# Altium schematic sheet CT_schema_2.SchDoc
size 461 x 297 mm
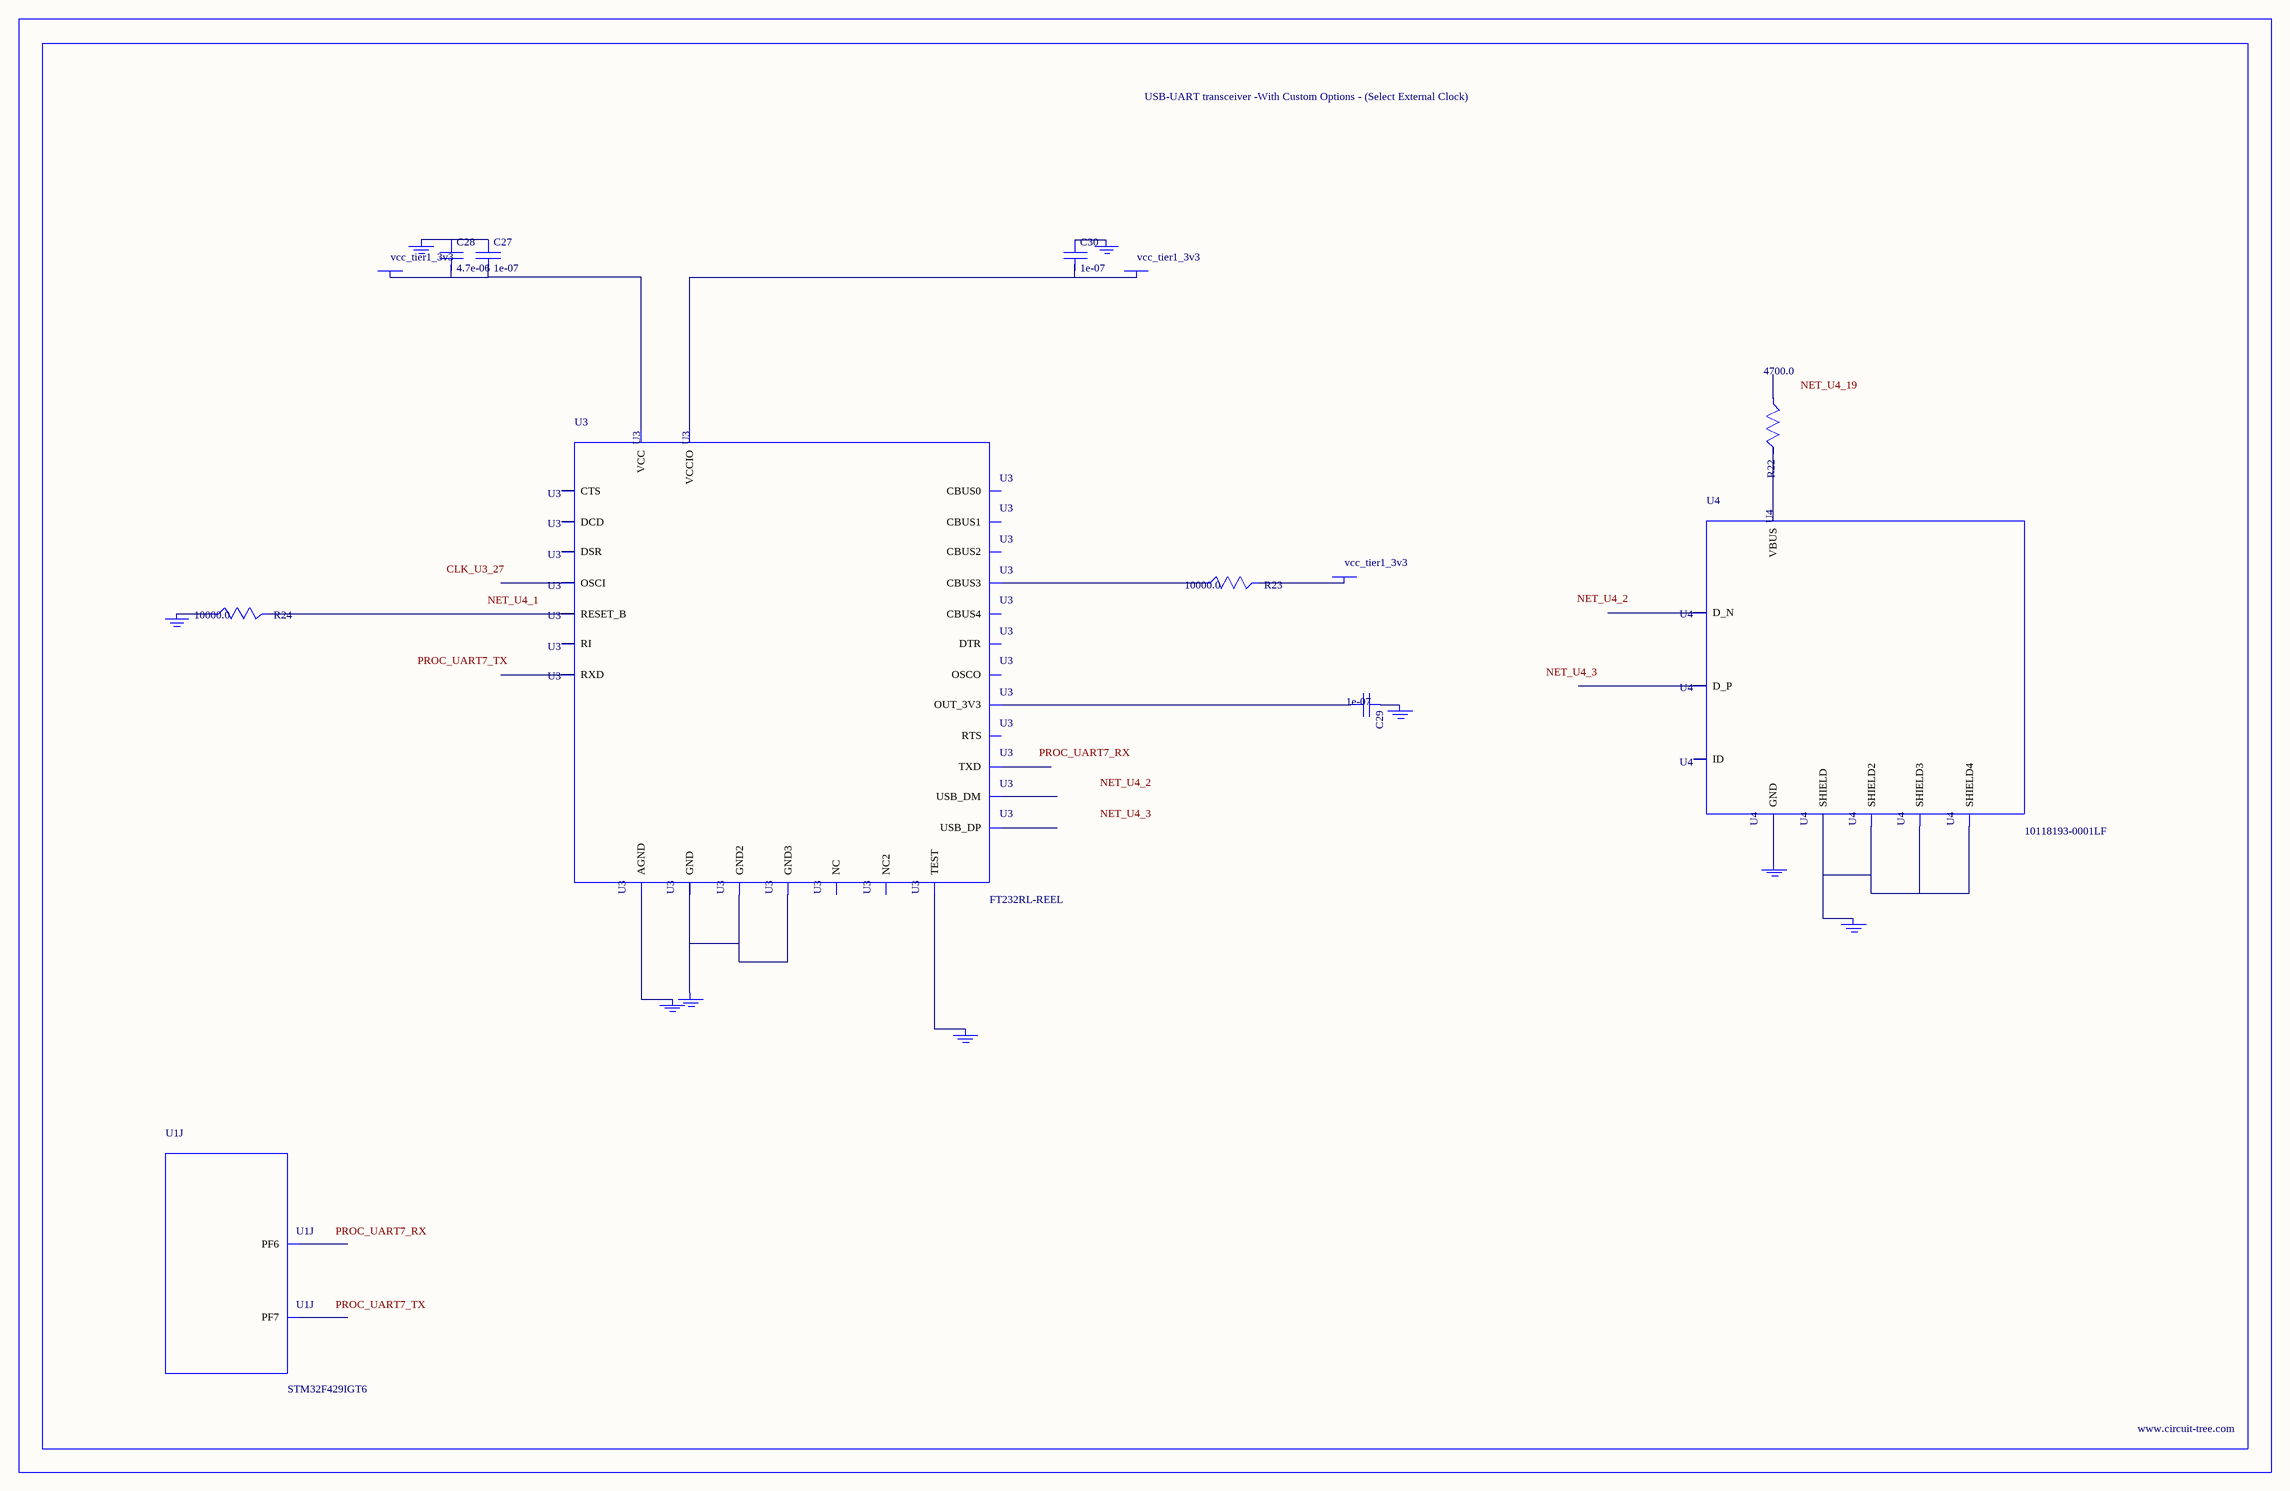
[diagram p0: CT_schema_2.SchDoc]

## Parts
BORDER1  (no value)
C27  1e-07  [C0402]
C28  4.7e-06  [C0805]
C29  1e-07  [C0402]
C30  1e-07  [C0402]
GND_INSTANCE_1_0  (no value)
GND_INSTANCE_1_1  (no value)
GND_INSTANCE_1_2  (no value)
GND_INSTANCE_1_3  (no value)
GND_INSTANCE_1_4  (no value)
GND_INSTANCE_1_5  (no value)
GND_INSTANCE_1_6  (no value)
GND_INSTANCE_1_7  (no value)
GND_INSTANCE_1_8  (no value)
POWER_INSTANCE_1_0  vcc_tier1_3v3
POWER_INSTANCE_1_1  vcc_tier1_3v3
POWER_INSTANCE_1_2  vcc_tier1_3v3
R22  4700.0  [R0603]
R23  10000.0  [R0603]
R24  10000.0  [R0603]
U1  STM32F429IGT6  [LQFP176]  (part J of 15)
U3  FT232RL-REEL  [SSOP-28]
U4  10118193-0001LF  [FCI_10118193-0001LF]

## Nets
NetC27_1: C27.1 C28.1 GND_INSTANCE_1_3.0(GND)
NetC27_2: C27.2 C28.2 POWER_INSTANCE_1_2.0(PWR) U3.20(VCC)
NetC29_1: C29.1 GND_INSTANCE_1_1.0(GND)
NetC29_2: C29.2 U3.17(OUT_3V3)
NetC30_1: C30.1 GND_INSTANCE_1_0.0(GND)
NetC30_2: C30.2 POWER_INSTANCE_1_0.0(PWR) U3.4(VCCIO)
NetGND_INSTANCE_1_2_0: GND_INSTANCE_1_2.0(GND) R24.1
NetGND_INSTANCE_1_4_0: GND_INSTANCE_1_4.0(GND) U3.25(AGND)
NetGND_INSTANCE_1_5_0: GND_INSTANCE_1_5.0(GND) U3.26(TEST)
NetGND_INSTANCE_1_6_0: GND_INSTANCE_1_6.0(GND) U3.7(GND) U3.18(GND2) U3.21(GND3)
NetGND_INSTANCE_1_7_0: GND_INSTANCE_1_7.0(GND) U4.6(SHIELD) U4.7(SHIELD2) U4.8(SHIELD3) U4.9(SHIELD4)
NetGND_INSTANCE_1_8_0: GND_INSTANCE_1_8.0(GND) U4.5(GND)
NetPOWER_INSTANCE_1_1_0: POWER_INSTANCE_1_1.0(PWR) R23.2
NetR22_2: R22.2 U4.1(VBUS)
NetR23_1: R23.1 U3.14(CBUS3)
NetR24_2: R24.2 U3.19(RESET_B)

Not connected (* = marked no-connect by the designer): R22 1; U1 24(PF6) 25(PF7); U3 1(TXD) 2(DTR) 3(RTS) 5(RXD) 6(RI) 8(NC) 9(DSR) 10(DCD) 11(CTS) 12(CBUS4) 13(CBUS2) 15(USB_DP) 16(USB_DM) 22(CBUS1) 23(CBUS0) 24(NC2) 27(OSCI) 28(OSCO); U4 2(D_N) 3(D_P) 4(ID)

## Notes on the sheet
- Labels drawn without touching a wire or pin: CLK_U3_27, NET_U4_1, NET_U4_2, NET_U4_3, NET_U4_19, PROC_UART7_RX, PROC_UART7_TX

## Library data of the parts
BORDER1 = BORDER_PAGE1
C27 C29 C30 = C0402C104K3RACTU
C28 = C0805C475K4RACTU
GND_INSTANCE_1_0-GND_INSTANCE_1_8 = GND
POWER_INSTANCE_1_0-POWER_INSTANCE_1_2 = PWR
R22 = RC0603JR-074K7L
R23 R24 = RC0603JR-0710KL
